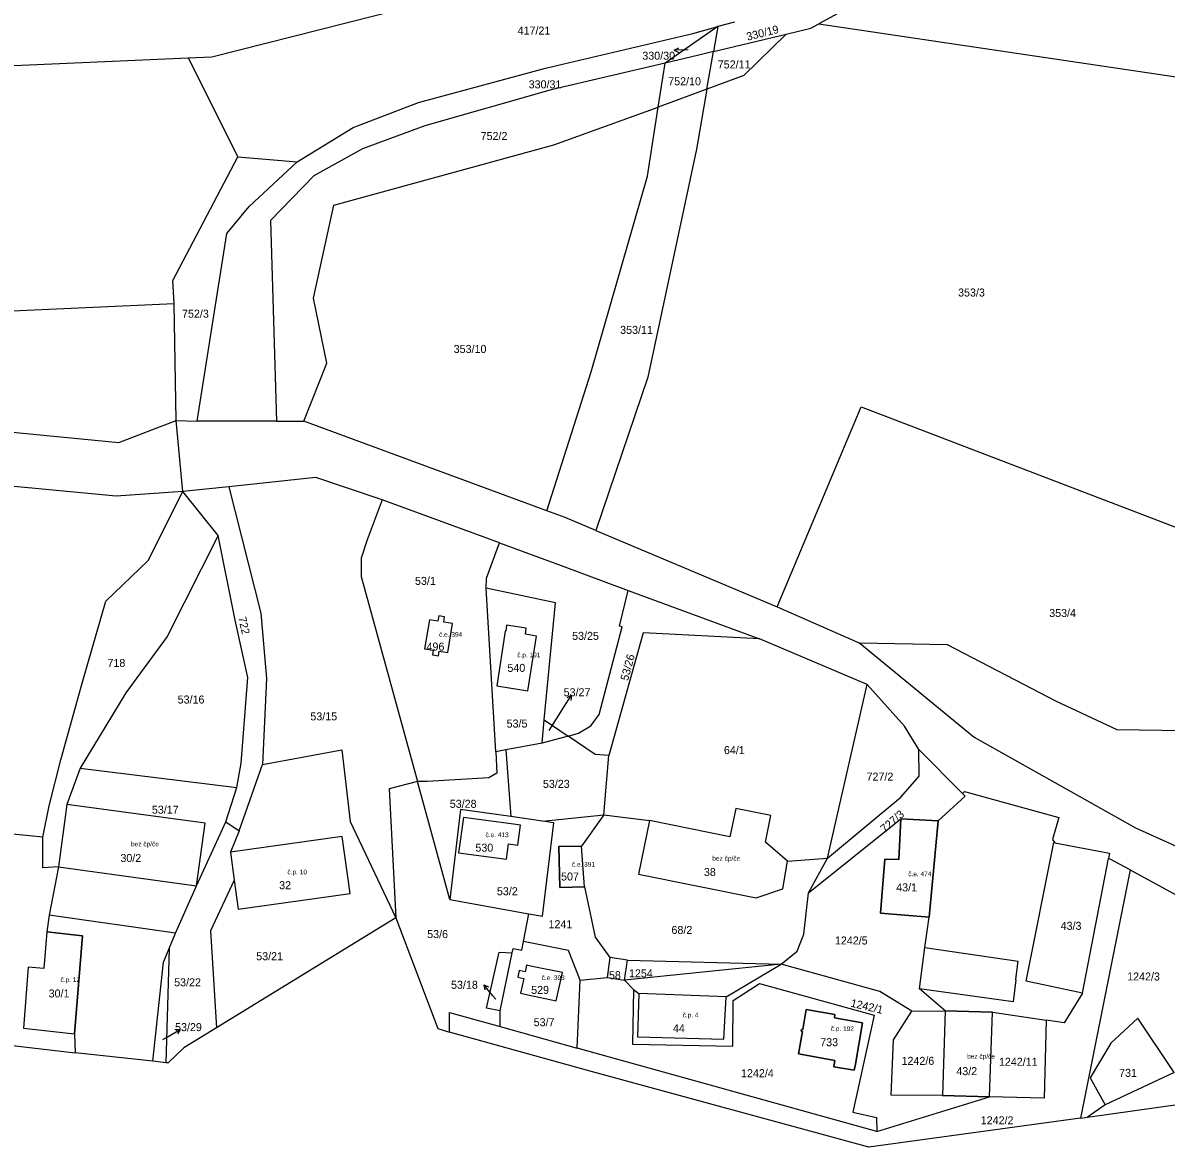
# Model space of a CAD drawing. Extents: x -887272 to -877616, y -1026687 to -1019819.
# Drawn here: x -883058.7 to -882815.9, y -1024101.6 to -1023862.8 of the extents above; entities that cross this region are included whole.
import ezdxf

# ---------------------------------------------------------------- set-up
doc = ezdxf.new("R2010")
doc.units = 0
for name, color, linetype in [('Definiční body', 7, 'Continuous'), ('Hranice parcel', 7, 'Continuous'), ('Parcelní čísla', 7, 'Continuous'), ('Polygon budovy', 7, 'Continuous'), ('Pop  PČ popisy', 7, 'Continuous'), ('Vnitřní kresba', 7, 'Continuous')]:
    doc.layers.add(name, color=color, linetype=linetype)

msp = doc.modelspace()

# ---------------------------------------------------------------- linework, layer by layer
at = {"layer": 'Hranice parcel'}
for p, q in [((-882911.11, -1023863.59), (-882922.29, -1023871.33)), ((-882916.42, -1023865.07), (-882911.11, -1023863.59)), ((-882911.11, -1023863.59), (-882912.04, -1023868.89)), ((-882907.61, -1023862.61), (-882911.11, -1023863.59)), ((-882889.66, -1023862.97), (-882740.58, -1023885.14)), ((-882912.04, -1023868.89), (-882896.59, -1023865.16)), ((-882896.59, -1023865.16), (-882905.58, -1023874)), ((-882912.04, -1023868.89), (-882915.14, -1023869.64)), ((-882913.45, -1023876.9), (-882912.04, -1023868.89)), ((-883023.64, -1023870.22), (-883013.08, -1023891.28)), ((-882923.77, -1023880.71), (-882922.29, -1023871.33)), ((-882915.14, -1023869.64), (-882922.29, -1023871.33)), ((-882905.58, -1023874), (-882913.45, -1023876.9)), ((-882913.45, -1023876.9), (-882923.77, -1023880.71)), ((-882945.96, -1023888.71), (-882923.77, -1023880.71)), ((-883013.08, -1023891.28), (-883000.47, -1023892.28)), ((-883006.13, -1023904.79), (-883004.83, -1023947.42)), ((-883021.73, -1023947.42), (-883015.44, -1023907.54)), ((-883178.1, -1023929.02), (-883026.61, -1023922.44)), ((-883026.2, -1023947.29), (-883026.61, -1023922.44)), ((-882947.44, -1023966.47), (-882938.02, -1023936.95)), ((-883038.36, -1023951.95), (-883026.2, -1023947.29)), ((-883026.2, -1023947.29), (-883021.73, -1023947.42)), ((-883024.78, -1023962.34), (-883026.2, -1023947.29)), ((-883004.83, -1023947.42), (-883021.73, -1023947.42)), ((-883004.83, -1023947.42), (-882999.02, -1023947.42)), ((-882947.44, -1023966.47), (-882999.02, -1023947.42)), ((-883014.98, -1023961.36), (-883024.78, -1023962.34)), ((-883017.26, -1023971.66), (-883024.78, -1023962.34)), ((-882943.56, -1023967.9), (-882947.44, -1023966.47)), ((-882937.06, -1023970.63), (-882943.56, -1023967.9)), ((-882937.06, -1023970.63), (-882898.5, -1023986.86)), ((-882986.9, -1023980.38), (-882974.9, -1024023.97)), ((-882958.29, -1024017.63), (-882960.3, -1023982.89)), ((-882930.15, -1023983.35), (-882902.29, -1023993.66)), ((-882898.5, -1023986.86), (-882881, -1023994.54)), ((-882879.44, -1024003.37), (-882902.29, -1023993.66)), ((-882887.84, -1024040.22), (-882879.44, -1024003.37)), ((-882948.46, -1024015.81), (-882947.99, -1024010.88)), ((-882947.99, -1024010.88), (-882942.92, -1024014.31)), ((-882942.92, -1024014.31), (-882948.46, -1024015.81)), ((-882942.92, -1024014.31), (-882940.69, -1024013.7)), ((-882937.16, -1024018.21), (-882942.92, -1024014.31)), ((-882948.46, -1024015.81), (-882956.15, -1024017.23)), ((-883007.84, -1024020.32), (-882990.97, -1024017.19)), ((-882956.15, -1024017.23), (-882958.29, -1024017.63)), ((-882956.15, -1024017.23), (-882955.08, -1024031.41)), ((-882934.25, -1024018.45), (-882937.16, -1024018.21)), ((-882935.36, -1024031), (-882934.25, -1024018.45)), ((-882859.19, -1024026.51), (-882868.46, -1024017.12)), ((-883046.55, -1024021.12), (-883049.37, -1024028.83)), ((-883046.55, -1024021.12), (-883013.3, -1024025.24)), ((-883012.76, -1024034.42), (-883007.84, -1024020.32)), ((-882974.9, -1024023.97), (-882980.91, -1024025.5)), ((-882968.02, -1024048.98), (-882974.9, -1024023.97)), ((-882972.85, -1024023.97), (-882974.9, -1024023.97)), ((-883015.61, -1024032.54), (-883013.3, -1024025.24)), ((-882980.91, -1024025.5), (-882979.5, -1024052.93)), ((-882859.19, -1024026.51), (-882858.74, -1024026.06)), ((-883049.37, -1024028.83), (-883051.19, -1024042.07)), ((-882948.36, -1024032.37), (-882955.08, -1024031.41)), ((-882948.36, -1024032.37), (-882935.36, -1024031)), ((-882935.36, -1024031), (-882940.06, -1024037.66)), ((-882935.36, -1024031), (-882925.68, -1024032.22)), ((-883021.84, -1024046.1), (-883015.61, -1024032.54)), ((-883015.61, -1024032.54), (-883012.76, -1024034.42)), ((-882891.9, -1024047.58), (-882872.26, -1024031.9)), ((-883012.76, -1024034.42), (-883014.66, -1024038.99)), ((-882944.88, -1024037.77), (-882940.06, -1024037.66)), ((-882944.68, -1024046.47), (-882944.88, -1024037.77)), ((-882939.43, -1024046.3), (-882940.06, -1024037.66)), ((-882839.57, -1024036.96), (-882827.96, -1024039.18)), ((-883014.66, -1024038.99), (-883013.83, -1024044.93)), ((-882896.32, -1024040.84), (-882887.84, -1024040.22)), ((-882891.9, -1024047.58), (-882887.84, -1024040.22)), ((-882833.66, -1024068.88), (-882828.18, -1024040.29)), ((-882827.96, -1024039.18), (-882828.18, -1024040.29)), ((-883051.19, -1024042.07), (-883053.13, -1024052.37)), ((-882823.53, -1024042.74), (-882834.12, -1024095.48)), ((-882823.53, -1024042.74), (-882793.44, -1024059.16)), ((-883026.3, -1024056.19), (-883021.84, -1024046.1)), ((-883013.83, -1024044.93), (-883018.87, -1024055.68)), ((-882939.43, -1024046.3), (-882944.68, -1024046.47)), ((-882968.02, -1024048.98), (-882951.29, -1024052.03)), ((-883026.3, -1024056.19), (-883053.13, -1024052.37)), ((-882979.5, -1024052.93), (-883017.57, -1024076.27)), ((-882979.5, -1024052.93), (-882970.63, -1024076.39)), ((-882952.42, -1024057.94), (-882951.29, -1024052.03)), ((-883018.87, -1024055.68), (-883017.57, -1024076.27)), ((-883027.64, -1024059.42), (-883026.3, -1024056.19)), ((-883027.64, -1024059.42), (-883028.33, -1024083.69)), ((-882957.34, -1024072.67), (-882954.78, -1024060.37)), ((-882954.78, -1024060.37), (-882954.57, -1024059.39)), ((-882934.05, -1024061.34), (-882934.66, -1024065.61)), ((-882930.35, -1024061.87), (-882934.05, -1024061.34)), ((-882930.96, -1024066.14), (-882930.35, -1024061.87)), ((-882897.65, -1024062.74), (-882930.96, -1024066.14)), ((-882930.35, -1024061.87), (-882897.65, -1024062.74)), ((-882940.36, -1024066.16), (-882934.66, -1024065.61)), ((-882934.66, -1024065.61), (-882930.96, -1024066.14)), ((-882940.98, -1024080.58), (-882940.36, -1024066.16)), ((-882930.96, -1024066.14), (-882929.03, -1024068.12)), ((-882833.66, -1024068.88), (-882845.63, -1024066.38)), ((-882929.03, -1024068.12), (-882927.92, -1024068.99)), ((-882957.35, -1024076.01), (-882957.34, -1024072.67)), ((-882869.92, -1024072.76), (-882862.86, -1024072.65)), ((-882862.86, -1024072.65), (-882863.45, -1024090.67)), ((-882862.86, -1024072.65), (-882852.82, -1024072.93)), ((-882853.42, -1024090.93), (-882852.82, -1024072.93)), ((-882852.82, -1024072.93), (-882841.37, -1024074.62)), ((-882841.37, -1024074.62), (-882841.8, -1024091.23)), ((-882970.63, -1024076.39), (-882968.15, -1024077.18)), ((-882957.35, -1024076.01), (-882940.98, -1024080.58)), ((-883031.12, -1024083.39), (-883047.64, -1024081.6)), ((-882877.4, -1024098.3), (-882940.98, -1024080.58)), ((-883028.33, -1024083.69), (-883031.12, -1024083.39)), ((-882814.22, -1024085.76), (-882828.88, -1024092.62)), ((-882877.4, -1024098.3), (-882853.42, -1024090.93)), ((-882853.42, -1024090.93), (-882863.45, -1024090.67)), ((-882841.8, -1024091.23), (-882853.42, -1024090.93)), ((-882832.64, -1024095.28), (-882813.04, -1024092.5)), ((-882828.88, -1024092.62), (-882832.64, -1024095.28)), ((-882834.12, -1024095.48), (-882832.64, -1024095.28))]:
    msp.add_line(p, q, dxfattribs=at)
for points in [[(-882814.51, -1023804.61), (-882840.14, -1023827.98), (-882853.74, -1023840.13), (-882872.92, -1023853.76), (-882889.66, -1023862.97)], [(-883023.64, -1023870.22), (-883018.61, -1023870), (-882937.74, -1023849.5), (-882908.79, -1023838.53), (-882874.84, -1023816.57)], [(-882896.59, -1023865.16), (-882891.36, -1023863.9), (-882889.66, -1023862.97)], [(-883000.47, -1023892.28), (-882988.57, -1023885.01), (-882974.72, -1023879.72), (-882947.73, -1023872.42), (-882916.42, -1023865.07)], [(-883093.7, -1023874.44), (-883086.38, -1023873.01), (-883023.64, -1023870.22)], [(-882922.29, -1023871.33), (-882946.52, -1023877.04), (-882973.33, -1023884.65), (-882986.6, -1023889.58), (-882996.92, -1023895.29), (-883006.13, -1023904.79)], [(-882913.45, -1023876.9), (-882915.68, -1023889.6), (-882926, -1023938.04), (-882937.06, -1023970.63)], [(-882938.02, -1023936.95), (-882926.08, -1023895.38), (-882923.77, -1023880.71)], [(-882999.02, -1023947.42), (-882994.2, -1023935.08), (-882996.98, -1023921.26), (-882992.7, -1023901.52), (-882945.96, -1023888.71)], [(-883026.61, -1023922.44), (-883026.88, -1023917.54), (-883013.08, -1023891.28)], [(-883015.44, -1023907.54), (-883010.67, -1023901.8), (-883000.47, -1023892.28)], [(-883188.08, -1023937.71), (-883148.98, -1023941.16), (-883038.36, -1023951.95)], [(-883024.78, -1023962.34), (-883038.88, -1023963.34), (-883149.62, -1023952.88), (-883229.75, -1023945.68)], [(-882898.5, -1023986.86), (-882880.66, -1023944.34), (-882783.22, -1023981.7)], [(-882982.44, -1023964.11), (-882996.5, -1023959.36), (-883014.98, -1023961.36)], [(-883054.46, -1024035.79), (-883053.12, -1024029.14), (-883050.64, -1024019.36), (-883046.02, -1024002.54), (-883041.08, -1023985.64), (-883032.14, -1023976.98), (-883024.78, -1023962.34)], [(-883014.98, -1023961.36), (-883008.22, -1023988.2), (-883006.98, -1024002.04), (-883007.84, -1024020.32)], [(-882982.44, -1023964.11), (-882985.61, -1023972.61), (-882986.9, -1023976.5), (-882986.9, -1023980.38)], [(-882957.52, -1023973.24), (-882960.99, -1023971.96), (-882982.44, -1023964.11)], [(-883017.26, -1023971.66), (-883028.08, -1023993.18), (-883036.86, -1024005.08), (-883046.55, -1024021.12)], [(-883013.3, -1024025.24), (-883012.38, -1024020.04), (-883010.94, -1024001.88), (-883013.66, -1023989.7), (-883017.26, -1023971.66)], [(-882960.3, -1023982.89), (-882960.28, -1023980.77), (-882957.52, -1023973.24)], [(-882957.52, -1023973.24), (-882944.43, -1023978.08), (-882930.15, -1023983.35)], [(-882947.99, -1024010.88), (-882945.62, -1023985.99), (-882960.3, -1023982.89)], [(-882940.69, -1024013.7), (-882938.13, -1024012.12), (-882936.36, -1024009.73), (-882931.42, -1023991.11), (-882932.04, -1023990.98), (-882930.15, -1023983.35)], [(-882973.42, -1023995.74), (-882971.6, -1023996.04), (-882971.76, -1023997.03), (-882970.48, -1023997.24), (-882970.32, -1023996.26), (-882968.5, -1023996.56), (-882967.47, -1023990.41), (-882969.34, -1023990.1), (-882969.16, -1023989), (-882970.39, -1023988.79), (-882970.57, -1023989.89), (-882972.39, -1023989.59), (-882973.42, -1023995.74)], [(-882952.01, -1023992.68), (-882951.81, -1023991.4), (-882955.98, -1023990.75), (-882956.18, -1023992.03), (-882956.28, -1023992.02), (-882958.08, -1024003.61), (-882951.46, -1024004.66), (-882949.64, -1023993.05), (-882952.01, -1023992.68)], [(-882902.29, -1023993.66), (-882927, -1023992.35), (-882934.25, -1024018.45)], [(-882793.94, -1024015.04), (-882803.56, -1024013.88), (-882812.08, -1024013.2), (-882826.3, -1024012.98), (-882839.2, -1024006.98), (-882862.38, -1023994.9), (-882881, -1023994.54)], [(-882881, -1023994.54), (-882856.7, -1024014.52), (-882822.42, -1024033.78), (-882792.42, -1024047.32), (-882777.72, -1024049.62), (-882760.86, -1024047.48), (-882725.1, -1024045.88)], [(-882868.46, -1024017.12), (-882871.52, -1024012.16), (-882879.44, -1024003.37)], [(-882990.97, -1024017.19), (-882989.22, -1024032.47), (-882979.5, -1024052.93)], [(-882958.29, -1024017.63), (-882958.05, -1024022.19), (-882959.79, -1024023.14), (-882972.85, -1024023.97)], [(-882887.84, -1024040.22), (-882872.24, -1024027.26), (-882868.34, -1024022.78), (-882868.46, -1024017.12)], [(-882872.26, -1024031.9), (-882864.37, -1024032.3), (-882858.64, -1024027.06), (-882859.19, -1024026.51)], [(-882858.74, -1024026.06), (-882838.7, -1024031.6), (-882840.05, -1024036.3), (-882839.57, -1024036.96)], [(-883021.84, -1024046.1), (-883020.04, -1024032.82), (-883049.37, -1024028.83)], [(-882955.08, -1024031.41), (-882965.78, -1024029.88), (-882968.02, -1024048.98)], [(-882965.17, -1024031.59), (-882966.2, -1024039.11), (-882956.01, -1024040.44), (-882955.57, -1024037.21), (-882953.61, -1024037.48), (-882953.04, -1024033.19), (-882954.99, -1024032.93), (-882965.17, -1024031.59)], [(-882896.32, -1024040.84), (-882901.04, -1024036.87), (-882899.89, -1024031.19), (-882907.33, -1024029.68), (-882908.55, -1024035.7), (-882925.68, -1024032.22)], [(-883054.46, -1024035.79), (-883074.51, -1024033.76), (-883078.86, -1024075.42)], [(-882951.29, -1024052.03), (-882948.35, -1024052.57), (-882945.98, -1024032.71), (-882948.36, -1024032.37)], [(-882925.68, -1024032.22), (-882928, -1024043.61), (-882902.98, -1024048.66)], [(-882862.86, -1024072.65), (-882868.28, -1024067.96), (-882867.18, -1024059.2), (-882866.22, -1024052.8), (-882876.6, -1024051.94), (-882875.68, -1024040.48), (-882872.72, -1024040.5), (-882872.26, -1024031.9)], [(-883051.19, -1024042.07), (-883054.48, -1024042.28), (-883054.46, -1024035.79)], [(-883013.83, -1024044.93), (-883012.97, -1024051.07), (-882989.21, -1024047.72), (-882990.9, -1024035.63), (-883014.66, -1024038.99)], [(-882845.63, -1024066.38), (-882839.81, -1024036.91), (-882839.57, -1024036.96)], [(-882902.98, -1024048.66), (-882897.34, -1024046.75), (-882896.32, -1024040.84)], [(-882823.53, -1024042.74), (-882827.92, -1024040.34), (-882828.18, -1024040.29)], [(-882939.43, -1024046.3), (-882937.18, -1024057.02), (-882934.05, -1024061.34)], [(-882897.65, -1024062.74), (-882894.28, -1024059.98), (-882892.84, -1024056.4), (-882891.9, -1024047.58)], [(-883053.13, -1024052.37), (-883053.65, -1024055.9), (-883054.3, -1024063.7), (-883057.6, -1024063.4), (-883058.62, -1024076.34), (-883047.78, -1024077.52), (-883047.64, -1024081.6)], [(-882954.57, -1024059.39), (-882952.77, -1024059.77), (-882952.42, -1024057.94)], [(-882940.36, -1024066.16), (-882942.84, -1024059.86), (-882952.42, -1024057.94)], [(-883031.12, -1024083.39), (-883028.86, -1024062.36), (-883027.64, -1024059.42)], [(-882957.34, -1024072.67), (-882960.29, -1024072.11), (-882957.57, -1024060.17), (-882954.78, -1024060.37)], [(-882951.49, -1024069.25), (-882945.45, -1024070.55), (-882944.15, -1024064.53), (-882950.18, -1024063.29), (-882951.74, -1024062.97), (-882952.04, -1024064.37), (-882953.3, -1024064.1), (-882953.61, -1024065.5), (-882952.35, -1024065.78), (-882953.03, -1024068.92), (-882951.49, -1024069.25)], [(-882909.85, -1024078.65), (-882909.39, -1024069.72), (-882897.65, -1024062.74)], [(-882869.92, -1024072.76), (-882876.73, -1024068.53), (-882897.65, -1024062.74)], [(-882929.03, -1024068.12), (-882929.25, -1024079.78), (-882907.96, -1024080.18), (-882907.89, -1024070.47), (-882902.29, -1024066.85), (-882877.91, -1024073.57), (-882882.43, -1024094.22), (-882877.41, -1024095.29), (-882877.4, -1024098.3)], [(-882927.92, -1024068.99), (-882928.16, -1024078.19), (-882909.85, -1024078.65)], [(-882833.66, -1024068.88), (-882837.6, -1024075.18), (-882841.37, -1024074.62)], [(-882893.33, -1024076.6), (-882893.09, -1024076.64), (-882892.35, -1024072.4), (-882886.27, -1024073.45), (-882886.38, -1024074.13), (-882880.42, -1024075.2), (-882881.93, -1024083.97), (-882882.15, -1024085.24), (-882886.52, -1024084.53), (-882886.28, -1024083.18), (-882893.99, -1024081.78), (-882893.16, -1024077.05), (-882893.4, -1024077.01), (-882893.33, -1024076.6)], [(-882863.45, -1024090.67), (-882874.34, -1024090.56), (-882873.85, -1024078.79), (-882869.92, -1024072.76)], [(-882968.15, -1024077.18), (-882968.13, -1024073.01), (-882957.35, -1024076.01)], [(-882814.22, -1024085.76), (-882821.92, -1024074.22), (-882827.7, -1024079.54), (-882832.06, -1024086.88), (-882828.88, -1024092.62)], [(-883078.86, -1024075.42), (-883067.68, -1024079.26), (-883047.64, -1024081.6)], [(-883017.57, -1024076.27), (-883024.54, -1024080.54), (-883027.89, -1024083.74), (-883028.33, -1024083.69)], [(-882834.12, -1024095.48), (-882879.1, -1024101.62), (-882937.74, -1024085.6), (-882968.15, -1024077.18)]]:
    msp.add_lwpolyline(points, dxfattribs=at)
at = {"layer": 'Polygon budovy'}
for points in [[(-882972.39, -1023989.59), (-882973.42, -1023995.74), (-882971.6, -1023996.04), (-882971.76, -1023997.03), (-882970.48, -1023997.24), (-882970.32, -1023996.26), (-882968.5, -1023996.56), (-882967.47, -1023990.41), (-882969.34, -1023990.1), (-882969.16, -1023989), (-882970.39, -1023988.79), (-882970.57, -1023989.89)], [(-882958.08, -1024003.61), (-882951.46, -1024004.66), (-882949.64, -1023993.05), (-882952.01, -1023992.68), (-882951.81, -1023991.4), (-882955.98, -1023990.75), (-882956.18, -1023992.03), (-882956.28, -1023992.02)], [(-883021.84, -1024046.1), (-883020.04, -1024032.82), (-883049.37, -1024028.83), (-883051.19, -1024042.07)], [(-882965.17, -1024031.59), (-882966.2, -1024039.11), (-882956.01, -1024040.44), (-882955.57, -1024037.21), (-882953.61, -1024037.48), (-882953.04, -1024033.19), (-882954.99, -1024032.93)], [(-882928, -1024043.61), (-882902.98, -1024048.66), (-882897.34, -1024046.75), (-882896.32, -1024040.84), (-882901.04, -1024036.87), (-882899.89, -1024031.19), (-882907.33, -1024029.68), (-882908.55, -1024035.7), (-882925.68, -1024032.22)], [(-882872.72, -1024040.5), (-882875.68, -1024040.48), (-882876.6, -1024051.94), (-882866.22, -1024052.8), (-882864.37, -1024032.3), (-882872.26, -1024031.9)], [(-883014.66, -1024038.99), (-883013.83, -1024044.93), (-883012.97, -1024051.07), (-882989.21, -1024047.72), (-882990.9, -1024035.63)], [(-882940.06, -1024037.66), (-882944.88, -1024037.77), (-882944.68, -1024046.47), (-882939.43, -1024046.3)], [(-883058.62, -1024076.34), (-883047.78, -1024077.52), (-883046.06, -1024056.7), (-883053.65, -1024055.9), (-883054.3, -1024063.7), (-883057.6, -1024063.4)], [(-882944.15, -1024064.53), (-882950.18, -1024063.29), (-882951.74, -1024062.97), (-882952.04, -1024064.37), (-882953.3, -1024064.1), (-882953.61, -1024065.5), (-882952.35, -1024065.78), (-882953.03, -1024068.92), (-882951.49, -1024069.25), (-882945.45, -1024070.55)], [(-882927.92, -1024068.99), (-882928.16, -1024078.19), (-882909.85, -1024078.65), (-882909.39, -1024069.72)], [(-882893.99, -1024081.78), (-882886.28, -1024083.18), (-882886.52, -1024084.53), (-882882.15, -1024085.24), (-882881.93, -1024083.97), (-882880.42, -1024075.2), (-882886.38, -1024074.13), (-882886.27, -1024073.45), (-882892.35, -1024072.4), (-882893.09, -1024076.64), (-882893.33, -1024076.6), (-882893.4, -1024077.01), (-882893.16, -1024077.05)], [(-882862.86, -1024072.65), (-882863.45, -1024090.67), (-882853.42, -1024090.93), (-882852.82, -1024072.93)]]:
    msp.add_lwpolyline(points, close=True, dxfattribs=at)
at = {"layer": 'Pop  PČ popisy'}
for p, q in [((-882920.41, -1023868.58), (-882919.42, -1023868.06)), ((-882917.41, -1023868.53), (-882920.41, -1023868.58)), ((-882920.41, -1023868.58), (-882919.4, -1023869.07)), ((-882943.81, -1024008.16), (-882942.22, -1024005.61)), ((-882942.22, -1024005.61), (-882943.18, -1024006.2)), ((-882942.22, -1024005.61), (-882942.33, -1024006.73)), ((-882946.95, -1024013.12), (-882943.81, -1024008.16)), ((-882958.94, -1024069.45), (-882960.83, -1024067.12)), ((-882960.83, -1024067.12), (-882959.81, -1024067.58)), ((-882960.83, -1024067.12), (-882960.59, -1024068.21)), ((-882958.31, -1024070.22), (-882958.94, -1024069.45)), ((-883027.9, -1024078.11), (-883025.3, -1024076.61)), ((-883025.3, -1024076.61), (-883026.42, -1024076.68)), ((-883025.3, -1024076.61), (-883025.92, -1024077.54)), ((-883029, -1024078.74), (-883027.9, -1024078.11))]:
    msp.add_line(p, q, dxfattribs=at)
at = {"layer": 'Vnitřní kresba'}
for p, q in [((-882864.37, -1024032.3), (-882866.22, -1024052.8)), ((-883051.19, -1024042.07), (-883021.84, -1024046.1)), ((-883053.65, -1024055.9), (-883046.06, -1024056.7)), ((-883046.06, -1024056.7), (-883047.78, -1024077.52)), ((-882867.18, -1024059.2), (-882847.32, -1024062.1)), ((-882847.82, -1024065.92), (-882847.32, -1024062.1)), ((-882848.44, -1024070.72), (-882868.28, -1024067.96)), ((-882847.84, -1024066.1), (-882848.44, -1024070.72)), ((-882847.84, -1024066.1), (-882847.82, -1024065.92)), ((-882909.39, -1024069.72), (-882927.92, -1024068.99))]:
    msp.add_line(p, q, dxfattribs=at)

# ---------------------------------------------------------------- texts
at = {"layer": 'Definiční body'}
for s, p in [('č.e. 394', (-882970.34, -1023993.21)), ('č.p. 191', (-882953.72, -1023997.56)), ('č.e. 413', (-882960.47, -1024035.77)), ('bez čp/če', (-883035.75, -1024037.73)), ('č.e. 391', (-882942.14, -1024042.04)), ('bez čp/če', (-882912.3, -1024040.79)), ('č.p. 10', (-883002.53, -1024043.66)), ('č.e. 474', (-882870.7, -1024044.07)), ('č.p. 12', (-883050.73, -1024066.53)), ('č.e. 393', (-882948.56, -1024066.13)), ('č.p. 4', (-882918.61, -1024074.06)), ('č.p. 192', (-882887.15, -1024076.96)), ('bez čp/če', (-882858.19, -1024082.82))]:
    msp.add_text(s, height=1, dxfattribs=at).set_placement(p)
at = {"layer": 'Parcelní čísla'}
for s, p in [('417/21', (-882953.66, -1023865.28)), ('330/30', (-882927.17, -1023870.62)), ('752/11', (-882911.15, -1023872.47)), ('330/31', (-882951.31, -1023876.7)), ('752/10', (-882921.67, -1023876.05)), ('752/2', (-882961.51, -1023887.68)), ('353/3', (-882860.11, -1023920.92)), ('752/3', (-883024.92, -1023925.42)), ('353/11', (-882931.88, -1023928.86)), ('353/10', (-882967.23, -1023932.91)), ('53/1', (-882975.45, -1023982.18)), ('353/4', (-882840.76, -1023989)), ('53/25', (-882942.08, -1023993.86)), ('496', (-882973, -1023996.14)), ('718', (-883040.76, -1023999.61)), ('540', (-882955.82, -1024000.66)), ('53/27', (-882943.88, -1024005.84)), ('53/16', (-883025.85, -1024007.38)), ('53/15', (-882997.67, -1024010.96)), ('53/5', (-882955.99, -1024012.49)), ('64/1', (-882909.84, -1024018.13)), ('53/23', (-882948.28, -1024025.3)), ('727/2', (-882879.55, -1024023.76)), ('53/17', (-883031.33, -1024030.78)), ('53/28', (-882968.06, -1024029.54)), ('530', (-882962.62, -1024038.85)), ('30/2', (-883038.01, -1024041.05)), ('507', (-882944.43, -1024044.98)), ('38', (-882914.09, -1024044.02)), ('32', (-883004.3, -1024046.83)), ('43/1', (-882873.25, -1024047.29)), ('53/2', (-882958.05, -1024048.11)), ('1241', (-882947.09, -1024055.11)), ('53/6', (-882972.86, -1024057.21)), ('68/2', (-882920.98, -1024056.33)), ('43/3', (-882838.33, -1024055.46)), ('1242/5', (-882886.27, -1024058.57)), ('53/21', (-883009.16, -1024061.91)), ('58', (-882934.26, -1024065.94)), ('1254', (-882930.01, -1024065.55)), ('1242/3', (-882824.2, -1024066.22)), ('30/1', (-883053.25, -1024069.82)), ('53/22', (-883026.6, -1024067.45)), ('53/18', (-882967.79, -1024067.98)), ('529', (-882950.78, -1024069.07)), ('53/29', (-883026.4, -1024076.98)), ('53/7', (-882950.24, -1024075.93)), ('44', (-882920.67, -1024077.22)), ('733', (-882889.39, -1024080.18)), ('1242/6', (-882872.12, -1024084.14)), ('1242/11', (-882851.44, -1024084.33)), ('1242/4', (-882906.21, -1024086.76)), ('43/2', (-882860.48, -1024086.33)), ('731', (-882825.92, -1024086.69)), ('1242/2', (-882855.3, -1024096.77))]:
    msp.add_text(s, height=1.7, dxfattribs=at).set_placement(p)
for s, rotation, p in [('330/19', 14, (-882904.81, -1023866.59)), ('722', 283, (-883013.01, -1023989.15)), ('53/26', 75, (-882930.21, -1024002.66)), ('727/3', 41, (-882875.68, -1024034.89)), ('1242/1', 347, (-882883.04, -1024071.76))]:
    msp.add_text(s, height=1.7, rotation=rotation, dxfattribs=at).set_placement(p)

doc.saveas('drawing.dxf')
